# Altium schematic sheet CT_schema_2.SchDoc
size 357 x 214 mm
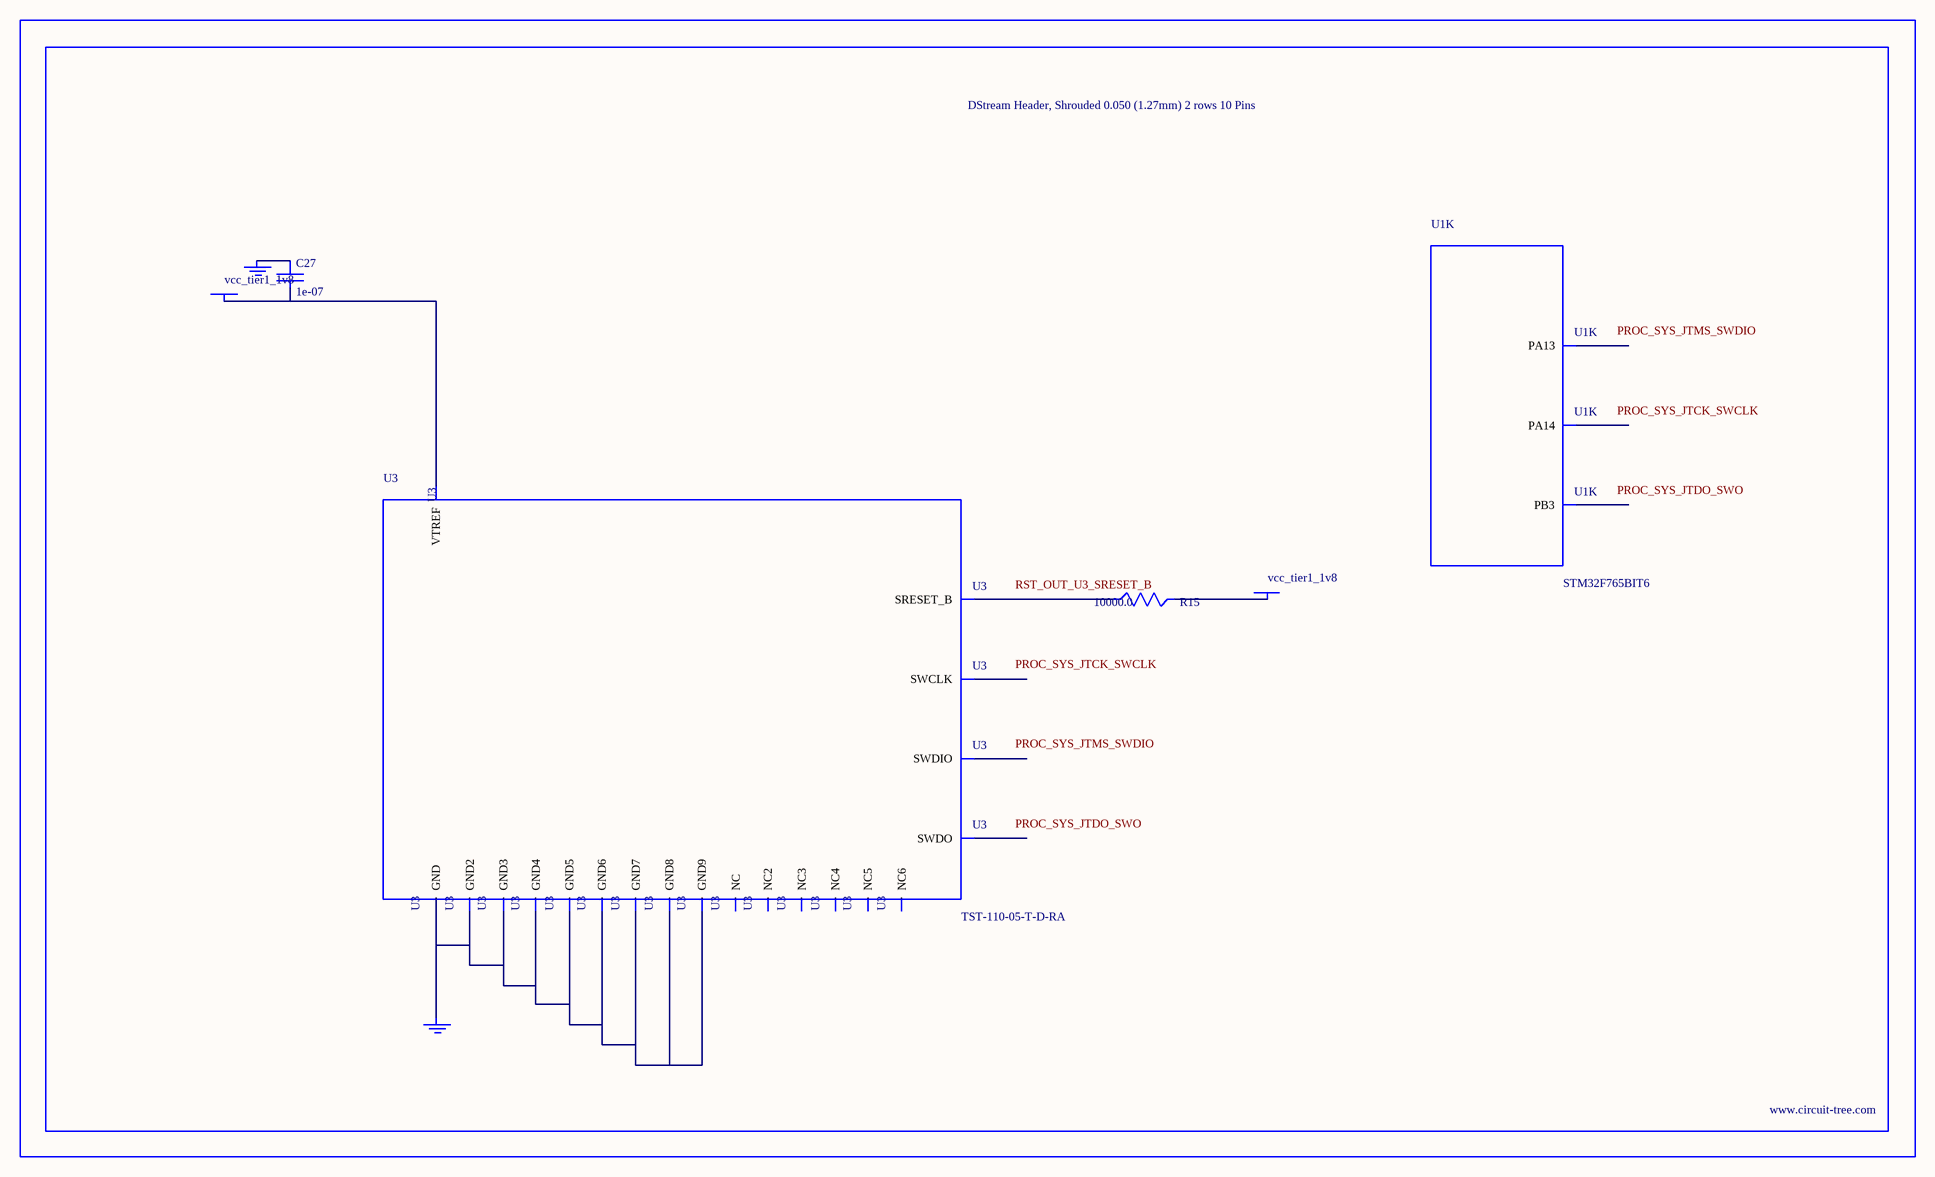
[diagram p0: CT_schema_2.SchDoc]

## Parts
BORDER1  (no value)
C27  1e-07  [C0402]
GND_INSTANCE_1_0  (no value)
GND_INSTANCE_1_1  (no value)
POWER_INSTANCE_1_0  vcc_tier1_1v8
POWER_INSTANCE_1_1  vcc_tier1_1v8
R15  10000.0  [R0603]
U1  STM32F765BIT6  [LQFP208]  (part K of 17)
U3  TST-110-05-T-D-RA  [TST-110-05-T-D-RA]

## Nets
NetC27_1: C27.1 GND_INSTANCE_1_0.0(GND)
NetC27_2: C27.2 POWER_INSTANCE_1_0.0(PWR) U3.1(VTREF)
NetGND_INSTANCE_1_1_0: GND_INSTANCE_1_1.0(GND) U3.4(GND) U3.6(GND2) U3.8(GND3) U3.10(GND4) U3.12(GND5) U3.14(GND6) U3.16(GND7) U3.18(GND8) U3.20(GND9)
NetPOWER_INSTANCE_1_1_0: POWER_INSTANCE_1_1.0(PWR) R15.2
NetR15_1: R15.1 U3.15(SRESET_B)

Not connected (* = marked no-connect by the designer): U1 147(PA13) 159(PA14) 192(PB3); U3 2(NC) 3(NC2) 5(NC3) 7(SWDIO) 9(SWCLK) 11(NC4) 13(SWDO) 17(NC5) 19(NC6)

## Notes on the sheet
- Labels drawn without touching a wire or pin: PROC_SYS_JTCK_SWCLK, PROC_SYS_JTDO_SWO, PROC_SYS_JTMS_SWDIO, RST_OUT_U3_SRESET_B

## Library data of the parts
BORDER1 = BORDER_PAGE1
C27 = C0402C104K3RACTU
GND_INSTANCE_1_0 GND_INSTANCE_1_1 = GND
POWER_INSTANCE_1_0 POWER_INSTANCE_1_1 = PWR
R15 = RC0603JR-0710KL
